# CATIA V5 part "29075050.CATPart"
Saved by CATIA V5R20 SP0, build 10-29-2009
Part number: 29075050
Definition: NONE
Nomenclature: 29075050
Source: Unknown
Description: 29075050
Bounding box of the stored display mesh (mm): x -25 to 44.548, y -51.5 to 86.048, z -41.5 to 41.5
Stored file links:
  C:\Users\Utente\Desktop\IO LAVORO\3D X SITO CF\X SITO\PLASTICA\RF1\29075050.CATPart
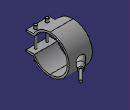
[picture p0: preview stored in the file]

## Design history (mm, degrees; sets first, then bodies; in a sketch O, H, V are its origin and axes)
Body1 "29075050" (main body)
  Solid1: solid without history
